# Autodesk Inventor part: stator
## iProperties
Shininess: 64.0
Length Units: 11269
Angle Units: 11279
Time Units: 11290
Mass Units: 11283
Length Display Precision: 3
Angle Display Precision: 2
Compacted: True
Part Number: stator
Document SubType Name: Modeling
Created: 2004-05
Material: Par défaut
Designer: David
Density: 0.0
Volumn: 0.0
Area: 0.0
PropertySet Name: Model Information
Control State: 0
Master: False
Checked Out: False
Author: David
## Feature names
1. Révolution1 [Revolution]
2. Congé1 [Fillet]
3. Congé2 [Fillet]
4. Extrusion1
5. Réseau circulaire1 [Circular Pattern]
6. Révolution2 [Revolution]
7. Congé3 [Fillet]
8. Réseau circulaire2 [Circular Pattern]
9. Extrusion2
10. Réseau circulaire3 [Circular Pattern]
11. Perçage1 [Hole]
